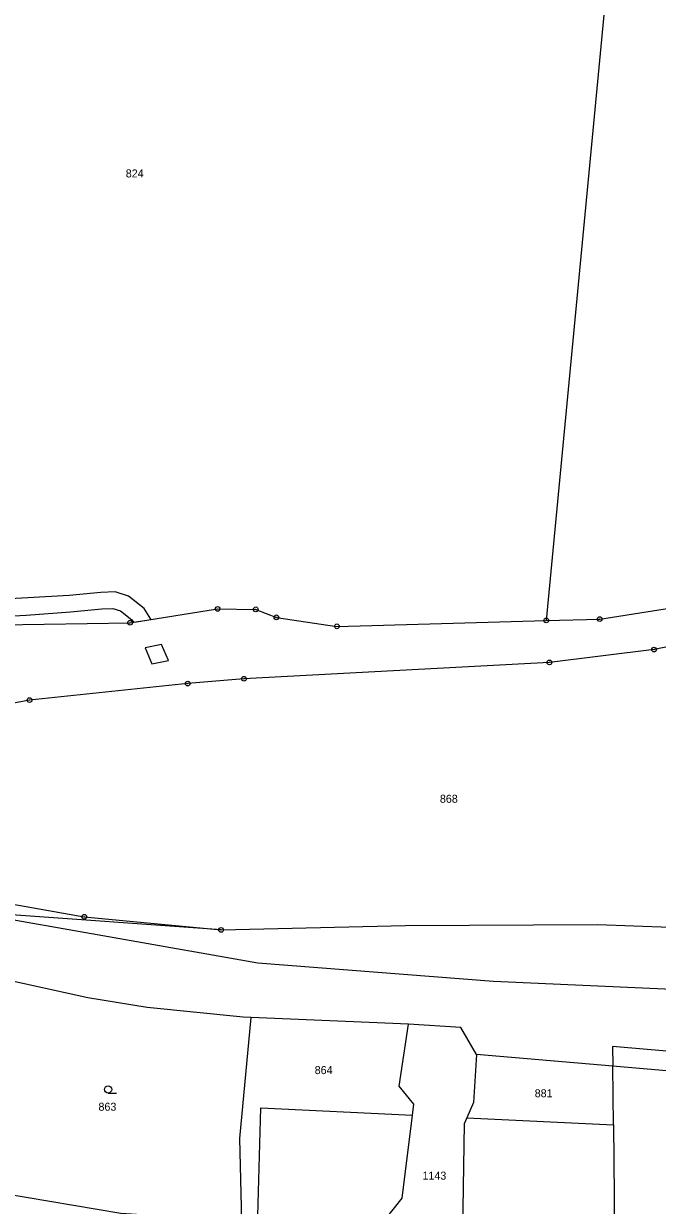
# Model space of a CAD drawing. Extents: x -758887 to -754328, y -1031688 to -1029144.
# Drawn here: x -756157.4 to -756022.6, y -1030298.3 to -1030047.3 of the extents above; entities that cross this region are included whole.
import ezdxf
from ezdxf.enums import TextEntityAlignment as Align

# ---------------------------------------------------------------- set-up
doc = ezdxf.new("R2010")
doc.units = 0
doc.header["$LTSCALE"] = 0.68
for name, color, linetype, lineweight in [('1', 7, 'Continuous', 25), ('13', 7, 'Continuous', 13), ('3', 7, 'Continuous', 25), ('8', 7, 'Continuous', 25)]:
    doc.layers.add(name, color=color, linetype=linetype, lineweight=lineweight)
doc.layers.add('2', color=7, linetype='Continuous')

msp = doc.modelspace()

# ---------------------------------------------------------------- linework, layer by layer
at = {"layer": '1'}
for p, q in [((-756029.98, -1030003.59), (-756046.25, -1030174.07)), ((-756115.36, -1030239.81), (-756168.69, -1030236.01)), ((-756075.54, -1030259.84), (-756108.96, -1030258.41)), ((-756031.94, -1030281.2), (-756031.56, -1030318.15))]:
    msp.add_line(p, q, dxfattribs=at)
for points in [[(-756046.25, -1030174.07), (-756034.87, -1030173.76), (-756011.1, -1030170.05), (-755976.5, -1030158.66), (-755951.32, -1030145.81), (-755930.64, -1030133.39), (-755882.12, -1030097.98), (-755845.97, -1030066.8), (-755842, -1030063.88)], [(-755912.98, -1030131.91), (-755941.48, -1030149.18), (-755969.92, -1030165.14), (-755979.24, -1030168.83), (-756000.09, -1030175.58), (-756023.31, -1030180.26), (-756045.55, -1030182.98), (-756110.5, -1030186.46), (-756122.46, -1030187.46), (-756156.09, -1030190.98), (-756180.89, -1030195.65), (-756198.51, -1030200.79), (-756212.93, -1030204.83), (-756215.25, -1030219.21), (-756200.88, -1030223.69), (-756172.51, -1030232.07), (-756144.45, -1030237.03), (-756115.36, -1030239.81)], [(-756115.36, -1030239.81), (-756076.17, -1030238.85), (-756035.35, -1030238.63), (-755996.69, -1030240.05), (-755922.34, -1030239.17), (-755912.98, -1030131.91)], [(-756240.69, -1030186.89), (-756231.02, -1030187.24), (-756214.93, -1030185.36), (-756201.16, -1030179.49), (-756187.28, -1030175.13), (-756162.13, -1030174.98), (-756134.72, -1030174.56), (-756116.1, -1030171.61), (-756107.99, -1030171.7), (-756103.62, -1030173.4), (-756090.76, -1030175.31), (-756046.25, -1030174.07)], [(-756108.96, -1030258.41), (-756110.66, -1030258.34), (-756131.11, -1030256.31), (-756143.73, -1030254.26), (-756162.39, -1030250.16), (-756184.91, -1030244.16), (-756213.6, -1030235.35)], [(-756168.69, -1030236.01), (-756107.58, -1030246.78), (-756057.43, -1030250.7), (-755984.58, -1030253.93), (-755948, -1030254.04), (-755899.3, -1030254.19), (-755881.67, -1030257.6), (-755833.91, -1030271.8), (-755782.97, -1030285.7), (-755758.24, -1030294.36)], [(-756171.95, -1030294.02), (-756136.72, -1030299.99), (-756110.94, -1030301.63), (-756111.35, -1030284.16), (-756108.96, -1030258.41)], [(-756074.7, -1030279.17), (-756074.42, -1030276.86), (-756077.49, -1030273.03), (-756075.54, -1030259.84)], [(-756061.08, -1030266.29), (-756064.43, -1030260.53), (-756075.54, -1030259.84)], [(-755738.96, -1030317.03), (-755781.06, -1030301.42), (-755875.65, -1030272.98), (-755900.13, -1030269), (-755986.93, -1030268.46), (-756032.15, -1030264.57), (-756032.07, -1030268.76)], [(-755868.93, -1030277.47), (-755871.21, -1030276.7), (-755898.99, -1030272.68), (-755975.93, -1030273.11), (-756019.91, -1030269.8), (-756032.07, -1030268.76)], [(-756106.51, -1030307.37), (-756107.65, -1030303.07), (-756106.9, -1030277.64), (-756074.7, -1030279.17)], [(-756078.24, -1030321.83), (-756083.22, -1030314.81), (-756082.01, -1030303.33), (-756076.85, -1030296.77), (-756074.7, -1030279.17)], [(-756063.12, -1030279.72), (-756063.67, -1030280.99), (-756064.16, -1030312.53), (-756068.18, -1030323.72), (-756031.56, -1030318.15)]]:
    msp.add_lwpolyline(points, dxfattribs=at)
msp.add_lwpolyline([(-756061.08, -1030266.29), (-756061.73, -1030276.5), (-756063.12, -1030279.72), (-756031.94, -1030281.2), (-756032.07, -1030268.76)], close=True, dxfattribs=at)
at = {"layer": '13'}
msp.add_lwpolyline([(-756180.1, -1030174.12), (-756156.78, -1030172.92), (-756147.39, -1030172.23), (-756140.75, -1030171.6), (-756138.37, -1030171.52), (-756136.75, -1030172.04), (-756134.34, -1030173.91), (-756134.01, -1030174.45), (-756130.27, -1030173.85), (-756130.29, -1030173.8), (-756131.7, -1030171.53), (-756135.09, -1030168.9), (-756137.87, -1030168), (-756140.97, -1030168.1), (-756147.68, -1030168.74), (-756180.38, -1030170.62)], dxfattribs=at)
msp.add_lwpolyline([(-756126.57, -1030182.59), (-756128.03, -1030179.14), (-756131.53, -1030179.85), (-756130.07, -1030183.3)], close=True, dxfattribs=at)
at = {"layer": '3'}
msp.add_line((-756139.383, -1030274.46), (-756137.633, -1030274.46), dxfattribs=at)
msp.add_circle((-756139.3829, -1030273.7098), 0.75, dxfattribs=at)
at = {"layer": '8'}
for centre, radius in [((-756116.1, -1030171.6099), 0.5), ((-756116.1, -1030171.6099), 0.0303), ((-756107.99, -1030171.6999), 0.5), ((-756107.99, -1030171.6999), 0.0303), ((-756134.72, -1030174.5599), 0.5), ((-756134.72, -1030174.5599), 0.0303), ((-756103.62, -1030173.3999), 0.5), ((-756103.62, -1030173.3999), 0.0303), ((-756090.76, -1030175.3099), 0.5), ((-756046.25, -1030174.0699), 0.5), ((-756046.25, -1030174.0699), 0.0303), ((-756034.87, -1030173.7599), 0.5), ((-756034.87, -1030173.7599), 0.0303), ((-756090.76, -1030175.3099), 0.0303), ((-756023.31, -1030180.2599), 0.5), ((-756023.31, -1030180.2599), 0.0303), ((-756045.55, -1030182.9799), 0.5), ((-756045.55, -1030182.9799), 0.0303), ((-756122.46, -1030187.4599), 0.5), ((-756122.46, -1030187.4599), 0.0303), ((-756110.5, -1030186.4599), 0.5), ((-756110.5, -1030186.4599), 0.0303), ((-756156.09, -1030190.9799), 0.5), ((-756156.09, -1030190.9799), 0.0303), ((-756144.45, -1030237.0299), 0.5), ((-756144.45, -1030237.0299), 0.0303), ((-756115.36, -1030239.8099), 0.5), ((-756115.36, -1030239.8099), 0.0303)]:
    msp.add_circle(centre, radius, dxfattribs=at)

# ---------------------------------------------------------------- texts
at = {"layer": '2'}
for s, p in [('824', (-756133.739, -1030079.936)), ('868', (-756066.949, -1030212.796)), ('864', (-756093.569, -1030270.446)), ('881', (-756046.789, -1030275.366)), ('863', (-756139.539, -1030278.226)), ('1143', (-756070.02, -1030292.866))]:
    msp.add_text(s, height=1.7, dxfattribs=at).set_placement(p, align=Align.CENTER)

doc.saveas('drawing.dxf')
